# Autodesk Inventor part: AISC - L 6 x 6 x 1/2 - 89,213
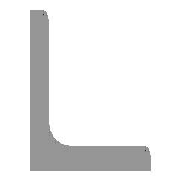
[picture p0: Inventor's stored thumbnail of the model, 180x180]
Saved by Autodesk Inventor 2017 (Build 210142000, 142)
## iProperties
_CCFamilyMember: 47
_CCFamilyDisplayName: ANSI L (Kątownik równoramienny) - Kątownik — Rozmiary w nawiasach zostały wycofane
_FrameMemberDoc: Frame Member File
_Version: 15.0.0
_GetPNFromCC: 1
Created: 2016-02
Part Number: AISC - L 6 x 6 x 1/2 - 89,213
Material: Stal, miękka
Description: Kątownik
Document SubType Name: Modeling
Standard: ANSI
Designer: X
Standards Organization: ANSI
Language: pl-PL
Size Designation: L 6 x 6 x 1/2
Categories: <MemberInstance><Categories><Category DisplayName="Kształtowniki konstrukcyjne" InternalName="089c4875-fa83-4c05-b084-43b9cc11f5ed" Mnemonic="GRDR"><CategoryPar
Stock Number: L 6 x 6 x 1/2
Density: 7.85 g/cm^3
Appearance: Częściowo polerowana
IsCustomPart: 1
G_L: 2266,000 mm
G_W: 152,400 mm
G_H: 152,400 mm
Author: X
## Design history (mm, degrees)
node "Płaszczyzna początkowa"
node "Płaszczyzna końcowa"
sketch "Szkic"
  geometry: L1 (152.4, 0)-(0, 0); L2 (0, 0)-(0, 152.4); L3 (0, 152.4)-(6.35, 152.4); L4 (12.7, 146.05)-(12.7, 25.4); L5 (25.4, 12.7)-(146.05, 12.7); L6 (152.4, 6.35)-(152.4, 0); L7 (0, -11.041)-(0, 31.538); L8 (-11.041, 0)-(31.538, 0); L9 (0, 186.666)-(0, -43.993) reference; L10 (-43.993, 0)-(186.666, 0) reference; A1 r 12.7 centre (25.4, 25.4) between (12.7, 25.4) and (25.4, 12.7); A2 r 6.35 centre (6.35, 146.05) between (12.7, 146.05) and (6.35, 152.4); A3 r 6.35 centre (146.05, 6.35) between (152.4, 6.35) and (146.05, 12.7); 3 further points
  constraints: 16 end point, 6 point on circle, 6 point on line, 6 tangent, 4 parallel, 3 centre point, 2 collinear, 1 equal radius, 1 horizontal, 1 perpendicular
  dimensions: "d0" = 152.4 distance between parallel lines of L6 L2 (= G_H); "d1" = 152.4 distance between parallel lines of L3 L1 (= G_H); "d2" = 12.7 distance between parallel lines of L2 L4 (= G_T); "d3" = 12.7 distance between parallel lines of L1 L5 (= G_T); "d10" = 0 distance between parallel lines of L7 L2 (computed from ex); "d11" = 0 distance between parallel lines of L8 L1 (computed from d10); "d14" = 12.7 radius of A1 (= G_IR); "d15" = 6.35 radius of A2 (= G_ER)
extrude "Bryła" new body sketch "Szkic" stored distance "d4" = 2266 (= G_L); taper "d5" = 0 deg
node "Driven Length"
  sketch "Sketch3"
    geometry: L1 (0, 0)-(10, 0) reference
    constraints: 2 end point, 1 horizontal
  workplane "Work Plane3"
  sketch "Sketch4"
    geometry: L1 (-2, -153)-(12, -153) reference; L2 (-2, 2113)-(12, 2113) reference
    dimensions: "d17" = 2266 distance between parallel lines of L1 L2 (derived)
body "Solid1"
other parameters: "G_H" = 152.4 [user parameter; used in 2 equation terms], "G_T" = 12.7 [user parameter; used in 2 equation terms], "G_ER" = 6.35 [user parameter; used in 1 equation term], "G_IR" = 12.7 [user parameter; used in 1 equation term], "G_L" = 2266 (= d17) [user parameter; used in 1 equation term], "ex" = 0 [user parameter; used in 1 equation term], "G_OFFSET_START" = 153 [user parameter; used in 1 equation term], "G_OFFSET_END" = 153 [user parameter; used in 1 equation term], "d12" = -153 (= -G_OFFSET_START), "d13" = 2113 (= G_OFFSET_END + B_L), "d16" = 90 deg, "MAS" = 2.9168 [user parameter]
